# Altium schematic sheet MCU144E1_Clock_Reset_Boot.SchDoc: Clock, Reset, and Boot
size 431 x 279 mm; DrawnBy: Gustavo Martinez; DocumentNumber: 7; SheetNumber: 4; SheetTotal: 8; PageSetup: Record=PageOptions¦CenterHorizontal=True¦CenterVertical=True¦PrintScale=1.00¦XCorrection=1.00¦YCorrection=1.00¦PrintKind=0¦BorderSize=5000000¦LeftOffset=0¦BottomOffset=0¦Orientation=2¦PaperLength=1000¦PaperWidth=1000¦Scale=100¦PaperSource=15¦PrintQuality=600¦MediaType=1¦DitherType=10¦PaperKind=Letter¦PrintScaleMode=1
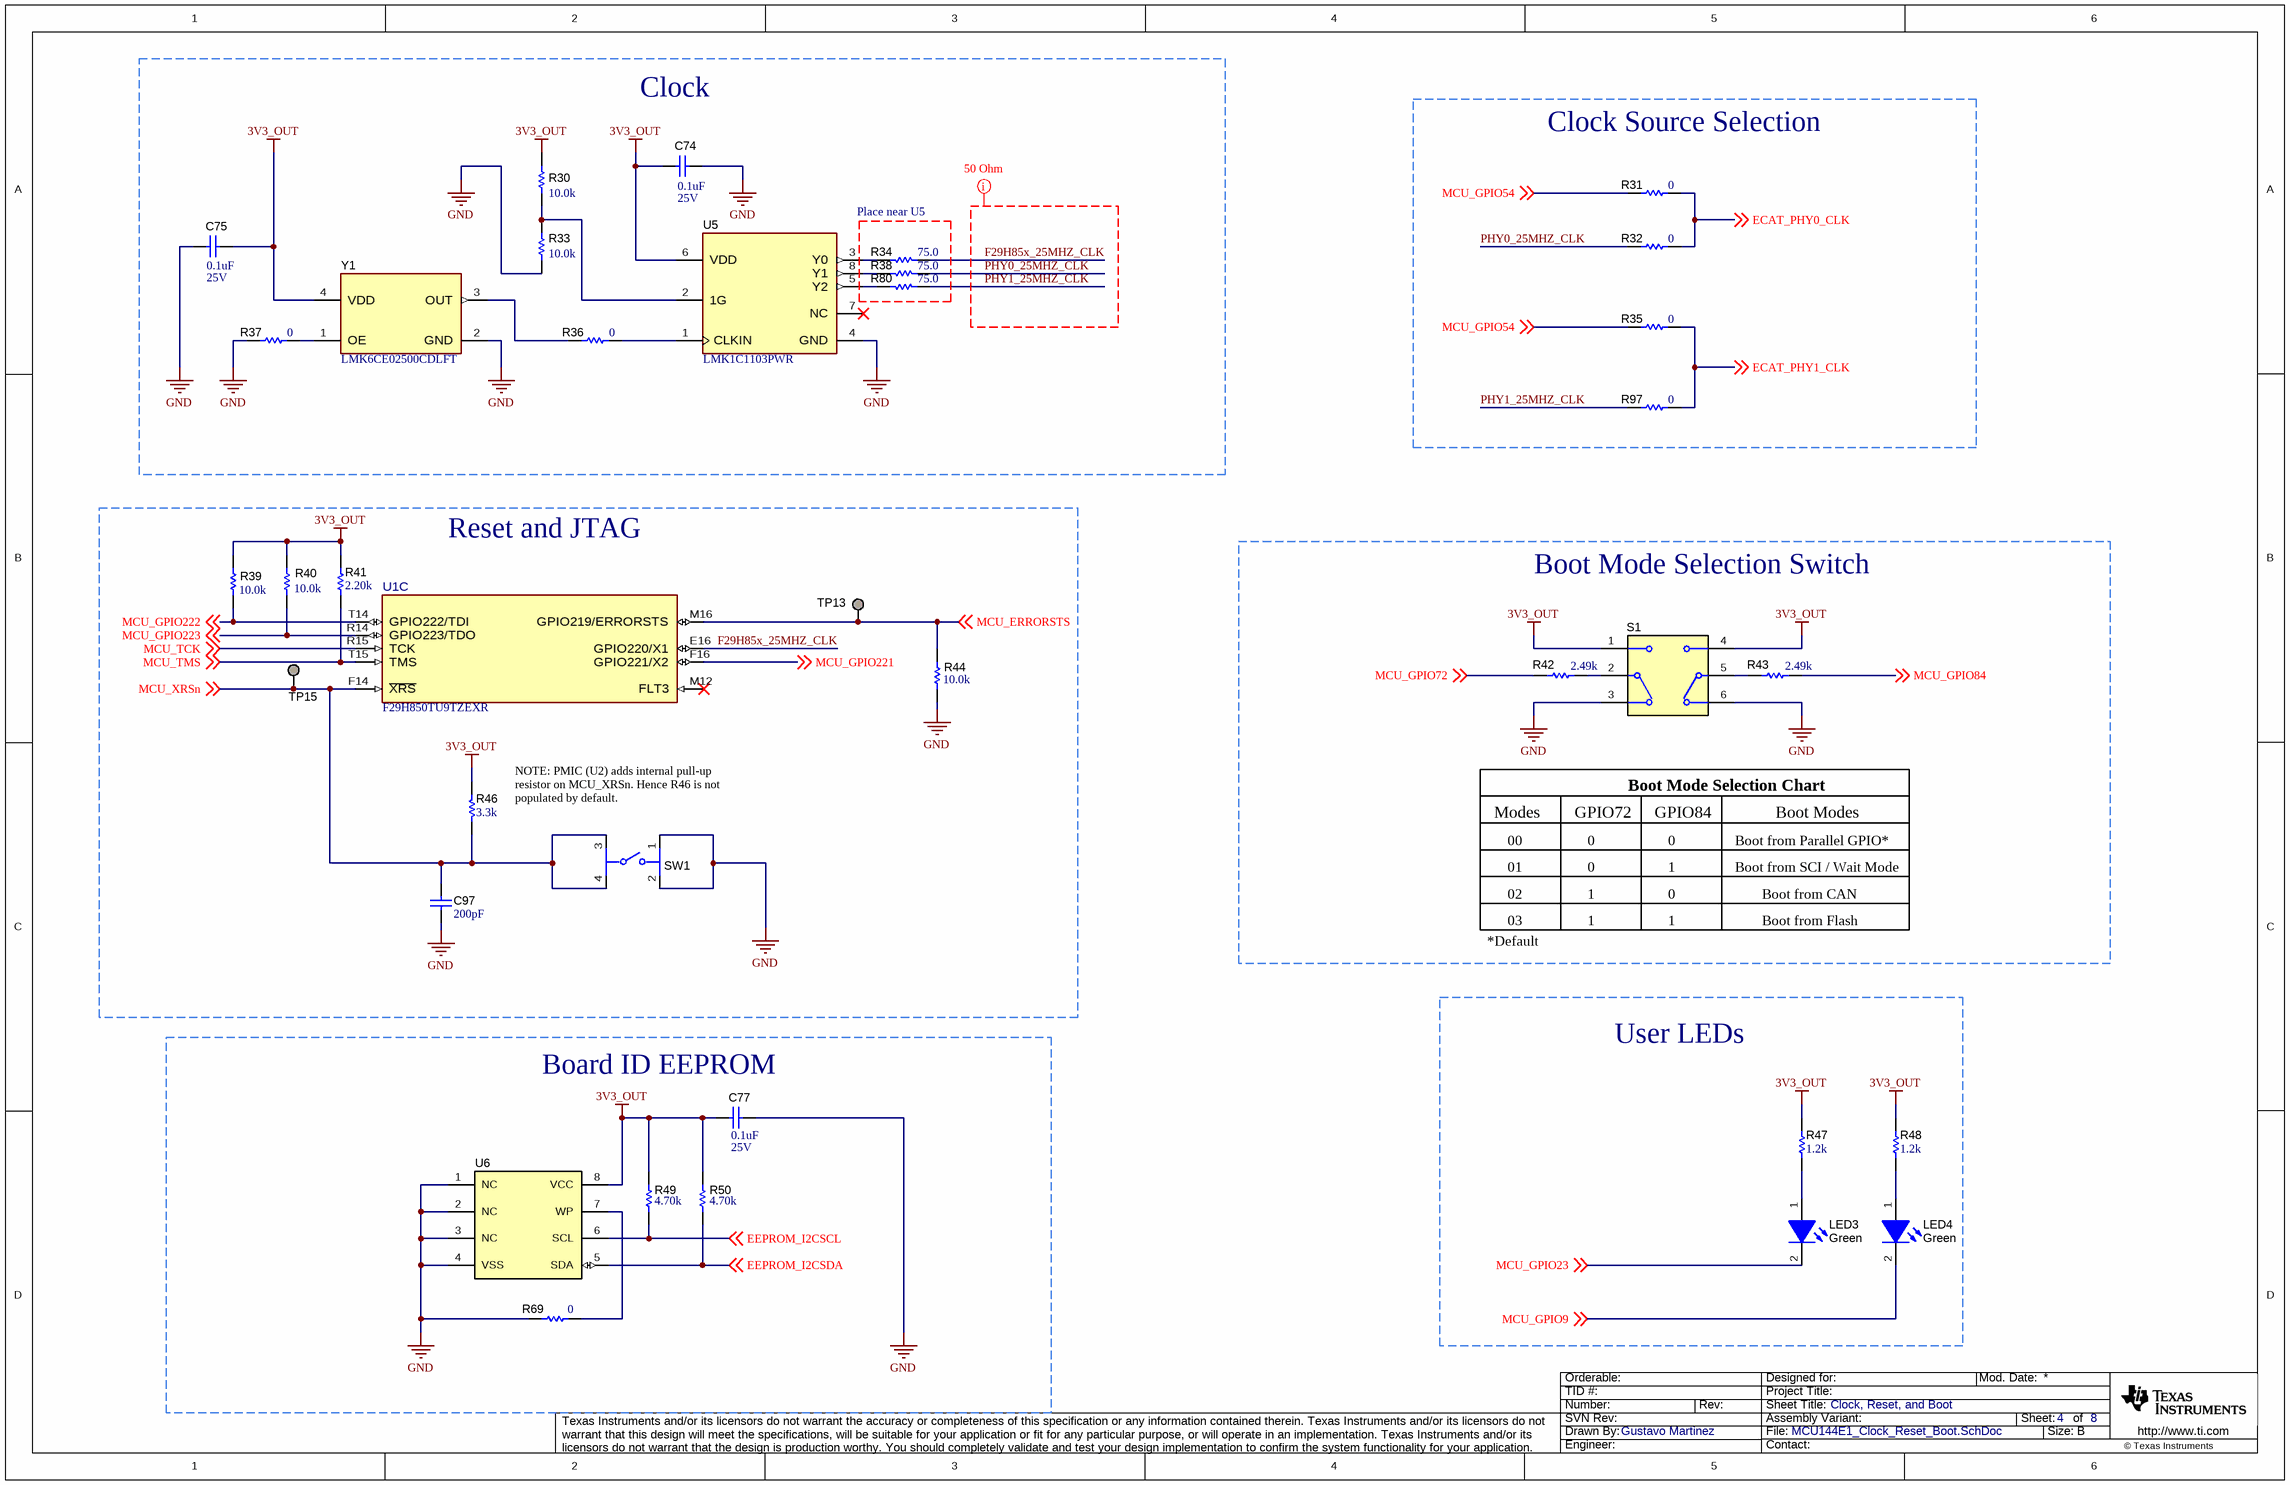
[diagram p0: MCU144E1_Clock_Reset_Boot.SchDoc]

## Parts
C74  VDC_V: 25V  ValueDisplayed: 0.1uF  [0402]  (hidden comment: GRM155R71E104KE14D)
C75  VDC_V: 25V  ValueDisplayed: 0.1uF  [0402]  (hidden comment: GRM155R71E104KE14D)
C77  VDC_V: 25V  ValueDisplayed: 0.1uF  [0402]  (hidden comment: GRM155R71E104KE14D)
C97  ValueDisplayed: 200pF  [0402]  (hidden comment: GRM1555C1H201JA01D)
LED3  value Green  [APHHS1005_Green]  (hidden comment: APHHS1005CGCK)
LED4  value Green  [APHHS1005_Green]  (hidden comment: APHHS1005CGCK)
R30  value 10.0k  [0402]  (hidden comment: AC0402FR-0710KL)
R31  value 0  [0402]  (hidden comment: CRCW04020000Z0ED)
R32  value 0  [0402]  (hidden comment: CRCW04020000Z0ED)
R33  value 10.0k  [0402]  (hidden comment: AC0402FR-0710KL)
R34  ValueDisplayed: 75.0  [0402]  (hidden comment: CRCW040275R0FKED)
R35  value 0  [0402]  (hidden comment: CRCW04020000Z0ED)
R36  ValueDisplayed: 0  [0402]  (hidden comment: CRCW04020000Z0ED)
R37  value 0  [0402]  (hidden comment: CRCW04020000Z0ED)
R38  ValueDisplayed: 75.0  [0402]  (hidden comment: CRCW040275R0FKED)
R39  value 10.0k  [0402]  (hidden comment: AC0402FR-0710KL)
R40  value 10.0k  [0402]  (hidden comment: AC0402FR-0710KL)
R41  ValueDisplayed: 2.20k  [0402]  (hidden comment: CRCW04022K20FKED)
R42  ValueDisplayed: 2.49k  [0402]  (hidden comment: CRCW04022K49FKED)
R43  ValueDisplayed: 2.49k  [0402]  (hidden comment: CRCW04022K49FKED)
R44  value 10.0k  [0402]  (hidden comment: AC0402FR-0710KL)
R46  ValueDisplayed: 3.3k  [0402]  (hidden comment: CRCW04023K30JNED)
R47  ValueDisplayed: 1.2k  [0402]  (hidden comment: CRCW04021K20JNED)
R48  ValueDisplayed: 1.2k  [0402]  (hidden comment: CRCW04021K20JNED)
R49  value 4.70k  [0402]  (hidden comment: CRG0402F4K7)
R50  value 4.70k  [0402]  (hidden comment: CRG0402F4K7)
R69  ValueDisplayed: 0  [0402]  (hidden comment: CRCW04020000Z0ED)
R80  ValueDisplayed: 75.0  [0402]  (hidden comment: CRCW040275R0FKED)
R97  value 0  [0402]  (hidden comment: CRCW04020000Z0ED)
S1  CAS-D20TA  [SW_CAS-D20TA]  (value not drawn)
SW1  PTS810 SJG 250 SMTR LFS  [FP-PTS810 SJG 250 SMTR LFS_SW_SMT_4MM2_3MM2-MFG]  (value not drawn)
TP13  TP_SM_1MM  [TP_SM_1MM]  (value not drawn)  (no BOM)
TP15  CMP-0078143-4  [TESTPOINT]  (value not drawn)  (no BOM)
U1  F29H850TU9TZEXR  [ZEX0256A-MFG]  (part C of 4)
U5  LMK1C1103PWR  [PW0008A-MFG]
U6  CAT24C16WI-GT3  [SOIC-8]  (value not drawn)
Y1  LMK6CE02500CDLFT  [DLF0004A-MFG]

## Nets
3V3_OUT: C74.1 C75.1 C77.1 R30.2 R39.2 R40.2 R41.2 R46.2 R47.2 R48.2 R49.2 R50.2 S1.1 S1.4 U5.6(VDD) U6.8(VCC) Y1.4(VDD)
GND: C74.2 C75.2 C77.2 C97.2 R33.1 R37.1 R44.1 R69.2 S1.3 S1.6 SW1.1 SW1.2 U5.4(GND) U6.1(NC) U6.2(NC) U6.3(NC) U6.4(VSS) Y1.2(GND)
ECAT_PHY0_CLK: R31.1 R32.1 ; off-sheet ECAT_PHY0_CLK
ECAT_PHY1_CLK: R35.1 R97.1 ; off-sheet ECAT_PHY1_CLK
EEPROM_I2CSCL: R49.1 U6.6(SCL) ; off-sheet EEPROM_I2CSCL
EEPROM_I2CSDA: R50.1 U6.5(SDA) ; off-sheet EEPROM_I2CSDA
F29H85x_25MHZ_CLK: R34.2 U1.E16(GPIO220/X1)
MCU_ERRORSTS: R44.2 TP13.1 U1.M16(GPIO219/ERRORSTS) ; off-sheet MCU_ERRORSTS
MCU_GPIO9: LED4.2(K) ; off-sheet MCU_GPIO9
MCU_GPIO23: LED3.2(K) ; off-sheet MCU_GPIO23
MCU_GPIO54: R31.2 R35.2 ; off-sheet MCU_GPIO54
MCU_GPIO72: R42.2 ; off-sheet MCU_GPIO72
MCU_GPIO84: R43.1 ; off-sheet MCU_GPIO84
MCU_GPIO221: U1.F16(GPIO221/X2) ; off-sheet MCU_GPIO221
MCU_GPIO222: R39.1 U1.T14(GPIO222/TDI) ; off-sheet MCU_GPIO222
MCU_GPIO223: R40.1 U1.R14(GPIO223/TDO) ; off-sheet MCU_GPIO223
MCU_TCK: U1.R15(TCK) ; off-sheet MCU_TCK
MCU_TMS: R41.1 U1.T15(TMS) ; off-sheet MCU_TMS
MCU_XRSn: C97.1 R46.1 SW1.3 SW1.4 TP15.1 U1.F14(~{XRS}) ; off-sheet MCU_XRSn
PHY0_25MHZ_CLK: R32.2 R38.2
PHY1_25MHZ_CLK: R80.2 R97.2
NetLED3_1: LED3.1(A) R47.1
NetLED4_1: LED4.1(A) R48.1
NetR30_1: R30.1 R33.2 U5.2(1G)
NetR34_1: R34.1 U5.3(Y0)
NetR36_1: R36.1 Y1.3(OUT)
NetR36_2: R36.2 U5.1(CLKIN)
NetR37_2: R37.2 Y1.1(OE)
NetR38_1: R38.1 U5.8(Y1)
NetR42_1: R42.1 S1.2(C)
NetR43_2: R43.2 S1.5(C)
NetR69_1: R69.1 U6.7(WP)
NetR80_1: R80.1 U5.5(Y2)

Not connected (* = marked no-connect by the designer): U1 M12(FLT3)*; U5 7(NC)*

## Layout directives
mark named 50 Ohm: 3V3_OUT, F29H85x_25MHZ_CLK, GND, PHY0_25MHZ_CLK, PHY1_25MHZ_CLK

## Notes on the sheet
- Clock
- Clock Source Selection
- Place near U5
- Reset and JTAG
- Boot Mode Selection Switch
- NOTE: PMIC (U2) adds internal pull-up resistor on MCU_XRSn. Hence R46 is not populated by default.
- Modes
- GPIO72
- Boot Mode Selection Chart
- GPIO84
- Boot Modes
- 00
- 01
- 02
- 0
- 1
- Boot from Parallel GPIO*
- Boot from SCI / Wait Mode
- Boot from CAN
- *Default
- 03
- Boot from Flash
- (near C77) Board ID EEPROM
- User LEDs

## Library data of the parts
C74 C75 C77 = CMP-0006659-2: CAP, CERM, 0.1 uF, 25 V, +/- 10%, X7R, 0402; Manufacturer: MuRata; TaMin_C: -55°C; Polarized: N; SizeAreaWB_mm2: 3; Value1: Unknown; U/M: EA; Value: 0.1uF; TaMax_C: 125°C; SizeZ_mm: 0.6; SizeX_mm: 1; SizeY_mm: 0.5; Cap_F: 100nF; AEC Category: Q200
C97 = CMP-0006437-2: CAP, CERM, 200 pF, 50 V, +/- 5%, C0G/NP0, 0402; Manufacturer: MuRata; TaMin_C: -55°C; Polarized: N; SizeAreaWB_mm2: 3; Value1: Unknown; U/M: EA; Value: 200pF; TaMax_C: 125°C; SizeZ_mm: 0.6; SizeX_mm: 1; SizeY_mm: 0.5; Value2: 50V; AEC Category: Q200
LED3 LED4 = CMP-0067682-2: LED, Green, SMD; Manufacturer: Kingbright; Value1: 0.075W; Vf_V: 2.1V; Vr_V: 5V; SizeArea_mm2: 0.5; Power_TotalModule: 75mW; Tjmax_C: 85°C; Angle: 120.0; SizeAreaWB_mm2: 3.0; SizeX_mm: 1.0; Ir_A: 10µA; Io_A: 20mA; SizeZ_mm: 0.6
R30 R33 R39 R40 R44 = CMP-0077731-1: RES, 10.0 k, 1%, 0.063 W, AEC-Q200 Grade 0, 0402; Manufacturer: Yageo America; Power_W: 63mW; TempCo: 100 ppm/C; Value_Code: 10k0; U/M: EA; EIA_Code: E96; Res_ohm: 10k; SizeX_mm: 1.0; SizeY_mm: 0.5; SizeZ_mm: 0.6; Value2: 0.063W; AEC Qualified: Y; VDC_V: 50V; AEC Grade: 0; AEC Category: Q200
R31 R32 R35 R37 R97 = CMP-0026822-3: RES, 0, 5%, 0.063 W, AEC-Q200 Grade 0, 0402; Manufacturer: Vishay-Dale; Power_W: 63mW; TempCo: 200 ppm/C; Value_Code: 0000; EIA_Code: E24; SizeX_mm: 1; SizeY_mm: 0.5; SizeZ_mm: 0.6; Value2: 0.063W; AEC Qualified: Y; VDC_V: 50V; AEC Category: Q200
R34 R38 R80 = CMP-0026544-2: RES, 75.0, 1%, 0.063 W, AEC-Q200 Grade 0, 0402; Manufacturer: Vishay-Dale; Power_W: 63mW; TempCo: 100 ppm/C; Value_Code: 75R0; Value: 75.0; EIA_Code: E96; Res_ohm: 75; SizeX_mm: 1; SizeY_mm: 0.5; SizeZ_mm: 0.6; Value2: 0.063W; AEC Qualified: Y; VDC_V: 50V; AEC Category: Q200; AEC Grade: 0
R36 R69 = CMP-0026822-3: RES, 0, 5%, 0.063 W, AEC-Q200 Grade 0, 0402; Manufacturer: Vishay-Dale; Power_W: 63mW; TempCo: 200 ppm/C; Value_Code: 0000; Value: 0; EIA_Code: E24; SizeX_mm: 1; SizeY_mm: 0.5; SizeZ_mm: 0.6; Value2: 0.063W; AEC Qualified: Y; VDC_V: 50V; AEC Category: Q200
R41 = CMP-0026231-2: RES, 2.20 k, 1%, 0.063 W, AEC-Q200 Grade 0, 0402; Manufacturer: Vishay-Dale; Power_W: 63mW; TempCo: 100 ppm/C; Value_Code: 2k20; Value: 2.20k; Res_ohm: 2.2k; SizeX_mm: 1; SizeY_mm: 0.5; SizeZ_mm: 0.6; Value2: 0.063W; AEC Qualified: Y; AEC Category: Q200; AEC Grade: 0
R42 R43 = CMP-0026237-2: RES, 2.49 k, 1%, 0.063 W, AEC-Q200 Grade 0, 0402; Manufacturer: Vishay-Dale; Power_W: 63mW; TempCo: 100 ppm/C; Value_Code: 2k49; Value: 2.49k; EIA_Code: E96; SizeX_mm: 1; SizeY_mm: 0.5; SizeZ_mm: 0.6; Value2: 0.063W; AEC Qualified: Y; VDC_V: 50V; AEC Category: Q200; AEC Grade: 0
R46 = CMP-0026918-5: RES, 3.3 k, 5%, 0.063 W, AEC-Q200 Grade 0, 0402; Manufacturer: Vishay-Dale; Power_W: 63mW; TempCo: 200 ppm/C; Value_Code: 3k30; Value: 3.3k; EIA_Code: E24; SizeX_mm: 1; SizeY_mm: 0.5; SizeZ_mm: 0.6; Value2: 0.063W; AEC Qualified: Y; VDC_V: 50V; AEC Category: Q200; AEC Grade: 0
R47 R48 = CMP-0026854-5: RES, 1.2 k, 5%, 0.063 W, AEC-Q200 Grade 0, 0402; Manufacturer: Vishay-Dale; Power_W: 63mW; TempCo: 200 ppm/C; Value_Code: 1k20; Value: 1.2k; EIA_Code: E24; SizeX_mm: 1; SizeY_mm: 0.5; SizeZ_mm: 0.6; Value2: 0.063W; AEC Qualified: Y; VDC_V: 50V; AEC Category: Q200; AEC Grade: 0
R49 R50 = CMP-0026631-1: RES, 4.70 k, 1%, 0.063 W, 0402; Manufacturer: TE Connectivity; Power_W: 63mW; TempCo: 100 ppm/C; Value_Code: 4k70; U/M: EA; Res_ohm: 4.7k; SizeX_mm: 1; SizeY_mm: 0.5; SizeZ_mm: 0.6; Value2: 0.063W; AEC Qualified: N; AEC Category: Q200
S1 = CMP-0002233-1: Switch, Dual SPDT,  2 Pos, 0.1A, 6VDC, SMD; Manufacturer: Copal Electronics; CurrentRating_mA: 100A; SwitchFunction: On-On; VDC_V: 6V; PositionCount: 2
SW1 = CMP-0087265-1: SWITCH TACTILE SPST-NO 0.05A 16V; Manufacturer: C&K Components; CurrentRating_mA: 50mA; SizeZ_mm: 2.7mm
TP13 = CMP-0003825-1: 1mm Test Point, SMT; Manufacturer: Any
TP15 = CMP-0078143-4: TEST POINT.  No entry in BOM.
U1 = CMP-0121934-2: Real-Time Microcontroller; Manufacturer: Texas Instruments; SizeZ_mm: 1.3mm; AEC Qualified: No; Core Architecture: C29x; Data Bus Width: 64bits; Frequency_Fixed: 200MHz; Interface: I2C,SPI,UART,CAN,LIN,IrDA,Other; Max Supply Voltage: 3.63V; Memory Size: 4MBytes; Memory Type: FLASH; Min Supply Voltage: 1.14V; Number Of A/D Converters: 5; Number Of Cores: 3; Number Of Ethernet Channels: 1; Number Of I2C Channels: 2; Number Of Pwm Channels: 36; Number Of Timers/Counters: 12; Number Of Uart Channels: 6; Ram Size: 452KBytes; Standoff Height: 0.25mm; TaMax_C: +105°C; TaMin_C: -40°C; TJmax_C: +125°C; AEC Category: Q200; CompType: IC
U5 = CMP-0094559-1: Clock Clock Buffer IC 1:3 250 MHz 8-TSSOP; Manufacturer: Texas Instruments; TaMax_C: +125°C; Propagation Delay: 1.5ns; SizeZ_mm: 1.2mm; TJmax_C: +150°C; Number Of Inputs: 1; Max Supply Voltage: 3.465V; Min Supply Voltage: 1.71V; Standoff Height: 0.05mm; Number Of Outputs: 3; AEC Qualified: No; TaMin_C: -40°C; Logic Function: Non-Inverting; Nominal Supply Current: 8-33mA
U6 = CMP-0082059-1: 16 Kb I2C EEPROM Serial, SOIC-8; Manufacturer: ON Semiconductor; SizeArea_mm2: 29.351; SizeAreaWB_mm2: 55.131; SizeY_mm: 4.9; SizeZ_mm: 1.75; SizeX_mm: 5.99
Y1 = CMP-0096024-2: High-Performance BAW Oscillator; Manufacturer: Texas Instruments; Load Capacitance: 30pF; TJmax_C: +125°C; Frequency Stability: 25ppm; SizeZ_mm: 1mm; Max Supply Current: 50mA; Min Supply Voltage: 2.375V; Standoff Height: 0mm; Frequency_Fixed: 25MHz; Max Supply Voltage: 3.465V; TaMax_C: +105°C; AEC Qualified: No; TaMin_C: -40°C; AEC Category: Q200; CompType: IC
